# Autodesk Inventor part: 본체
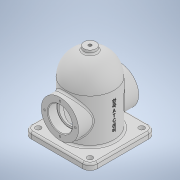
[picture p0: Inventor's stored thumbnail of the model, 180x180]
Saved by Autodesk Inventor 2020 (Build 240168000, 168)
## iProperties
Created: 2021-07
Part Number: 본체
Material: 일반
Document SubType Name: Modeling
Designer: Owner
Mass: 320.697 g
Surface Area: 800.663 cm^2
Volume: 320.697 cm^3
Density: 1 g/cm^3
Appearance: 기본값
Author: Owner
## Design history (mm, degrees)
sketch "스케치1"
  geometry: C1 r 40 at (0, 0); 1 further point
  constraints: 1 centre point, 1 coincident
  dimensions: "d0" = 80 diameter of C1
extrude "돌출1" new body sketch "스케치1" distance "d1" = 124; taper "d2" = 0 deg
fillet "모깎기1" dims "d3" = 40
feature "쉘1" dims "d4" = 8
sketch "스케치2"
  geometry: L1 (55, 55)-(-55, 55); L2 (-55, 55)-(-55, -55); L3 (-55, -55)-(55, -55); L4 (55, -55)-(55, 55); L5 (55, 55)-(-55, -55); L6 (-55, 55)-(55, -55); C1 r 32 at (0, 0) reference; 1 further point
  constraints: 12 end point, 2 midpoint, 2 parallel, 1 horizontal, 1 perpendicular
  dimensions: "d5" = 110 distance of L3.end L2.end; "d6" = 110 distance of L2.end L1.end
extrude "돌출2" join sketch "스케치2" distance "d7" = 10; taper "d8" = 0 deg
fillet "모깎기2" dims "d9" = 12
fillet "모깎기3" dims "d10" = 3
node "작업 평면1"
sketch "스케치3"
  geometry: C1 r 10 at (0, 0); 1 further point
  constraints: 1 centre point, 1 coincident
  dimensions: "d12" = 20 diameter of C1
extrude "돌출3" join sketch "스케치3" stored distance "d13" = 124; taper "d14" = 0 deg
sketch "스케치4"
  geometry: C1 r 10 at (0, 0) reference; 2 further points
  constraints: 1 coincident
hole "구멍1" sketch "스케치4" at (0, 0) diameter "d15" = 5.1881; stored, may be unused: countersink angle "d19" = 90 deg, drill point angle "d21" = 118 deg; dims "d16" = 30, "d17" = 8, "d18" = 10, "d20" = 16
node "작업 평면2"
sketch "스케치5"
  geometry: L1 (43, 0)-(-43, 0) reference; C1 r 31 at (0, 48); 2 further points
  constraints: 1 centre point, 1 midpoint, 1 vertical alignment
  dimensions: "d23" = 62 diameter of C1; "d24" = 48 distance from line of L1 C1.centre
extrude "돌출4" join sketch "스케치5" stored distance "d25" = 124; taper "d26" = 0 deg
sketch "스케치6"
  geometry: C1 r 31 at (0, 0) reference; 2 further points
  constraints: 1 coincident
hole "구멍2" sketch "스케치6" at (0, 0) diameter "d27" = 33; stored, may be unused: countersink angle "d31" = 90 deg, drill point angle "d33" = 118 deg; dims "d28" = 12, "d29" = 40, "d30" = 15, "d32" = 16
sketch "스케치7"
  geometry: L1 (43, -48)-(-43, -48) reference; C1 r 16.5 at (0, 0) reference; 3 further points
  constraints: 1 midpoint, 1 vertical alignment
  dimensions: "d34" = 25.5 distance of C1.centre point (0, 25.5)
hole "구멍3" sketch "스케치7" at (0, 25.5) diameter "d35" = 3.242; stored, may be unused: countersink angle "d39" = 90 deg, drill point angle "d41" = 118 deg; dims "d36" = 8, "d37" = 40, "d38" = 15, "d40" = 10
sketch "스케치8"
  geometry: A1 r 9 centre (-43, 43) between (-43, 52) and (-52, 43) reference; 2 further points
  constraints: 1 coincident
hole "구멍4" sketch "스케치8" at (-43, 43) diameter "d45" = 9; stored, may be unused: countersink angle "d49" = 90 deg, drill point angle "d51" = 118 deg; dims "d46" = 8, "d47" = 40, "d48" = 15, "d50" = 10
sketch "스케치9"
  geometry: A1 r 9 centre (43, 43) between (52, 43) and (43, 52) reference; 2 further points
  constraints: 1 coincident
hole "구멍5" sketch "스케치9" at (43, 43) diameter "d52" = 9; stored, may be unused: countersink angle "d56" = 90 deg, drill point angle "d58" = 118 deg; dims "d53" = 8, "d54" = 40, "d55" = 15, "d57" = 10
sketch "스케치10"
  geometry: A1 r 9 centre (-43, -43) between (-52, -43) and (-43, -52) reference; 2 further points
  constraints: 1 coincident
hole "구멍6" sketch "스케치10" at (-43, -43) diameter "d59" = 9; stored, may be unused: countersink angle "d63" = 90 deg, drill point angle "d65" = 118 deg; dims "d60" = 8, "d61" = 40, "d62" = 15, "d64" = 10
sketch "스케치11"
  geometry: A1 r 9 centre (43, -43) between (43, -52) and (52, -43) reference; 2 further points
  constraints: 1 coincident
hole "구멍7" sketch "스케치11" at (43, -43) diameter "d66" = 9; stored, may be unused: countersink angle "d70" = 90 deg, drill point angle "d72" = 118 deg; dims "d67" = 8, "d68" = 40, "d69" = 15, "d71" = 10
fillet "모깎기4" dims "d73" = 3
chamfer "모따기1" distance "d74" = 1; stored, may be unused: second distance "d75" = 2, angle "d76" = 45 deg
fillet "모깎기5" dims "d77" = 0.3
node "작업 평면3"
sketch "스케치12"
  geometry: L1 (0, -43)-(0, 43) reference; 3 further points
  constraints: 1 horizontal alignment, 1 midpoint, 1 other
  dimensions: "d79" = 48 distance from line of L1 point (48, 0)
feature "엠보싱1" sketch "스케치12" dims "d80" = 0.5, "d81" = 0
node "솔리드1"
mirror "미러1"
pattern_circular "원형 패턴1" dims angle "d43" = 360 deg
mirror "미러2"
feature "A9D066F2-1C7D-4E18-AEED-F7BC21143FA4" dims "d15" = 5.1881, "d16" = 30, "d17" = 8, "d18" = 10, "d19" = 90 deg, "d20" = 16, "d21" = 118 deg
other parameters: "d11" = 129
